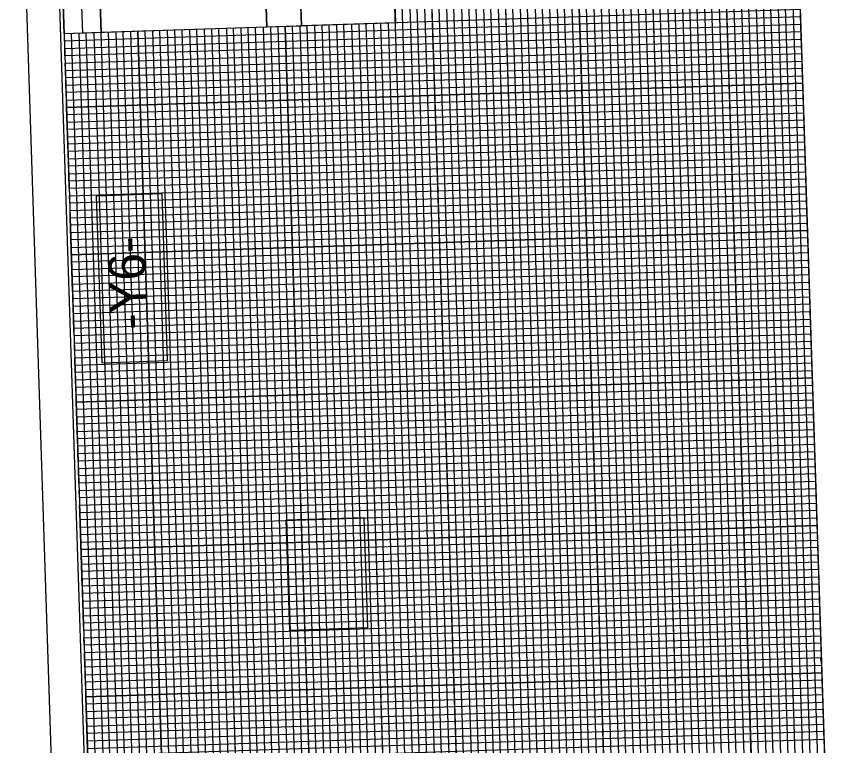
# Model space of a CAD drawing. Extents: x 1627314 to 1628469, y 762309 to 764247.
# Drawn here: x 1627314 to 1627864, y 763293 to 763788 of the extents above; entities that cross this region are included whole.
import ezdxf

# ---------------------------------------------------------------- set-up
doc = ezdxf.new("R2010")
doc.units = 0
for name, color, linetype in [('Old_Level_2', 7, 'Continuous'), ('Prop Grid Mask', 7, 'Continuous'), ('Sheet Data Field CELL', 7, 'Continuous'), ('Sheet DOT Grid CELL', 7, 'Continuous'), ('Sheet Layout Profile Border Port 1', 7, 'Continuous'), ('Sheet Plot Border Inside CELL', 7, 'Continuous'), ('Sheet Plot Border Outside CELL', 7, 'Continuous'), ('Sheet Profile CELL', 7, 'Continuous'), ('Sheet Profile Grid Major CELL', 7, 'Continuous'), ('Sheet Profile Grid Middle CELL', 7, 'Continuous'), ('Sheet Profile Grid Minor CELL', 7, 'Continuous'), ('Sheet Sticker Exception Certification CELL', 7, 'Continuous')]:
    doc.layers.add(name, color=color, linetype=linetype)

msp = doc.modelspace()

# ---------------------------------------------------------------- linework, layer by layer
at = {"layer": 'Old_Level_2'}
msp.add_lwpolyline([(1627507.79, 763781.61), (1627501.25, 763981.49), (1627565.16, 763983.58), (1627571.7, 763783.7)], close=True, dxfattribs=at)
at = {"layer": 'Prop Grid Mask'}
for points in [[(1627417.01, 763554.6), (1627413.31, 763667.62), (1627368.59, 763666.16), (1627372.29, 763553.14)], [(1627499.94, 763371.54), (1627497.49, 763446.59), (1627550.13, 763448.31), (1627552.58, 763373.26)]]:
    msp.add_lwpolyline(points, close=True, dxfattribs=at)
at = {"layer": 'Sheet DOT Grid CELL'}
for p, q in [((1627690.1, 763987.68), (1627739.13, 762488.48)), ((1627740.07, 763989.32), (1627789.11, 762490.12)), ((1627790.04, 763990.95), (1627839.08, 762491.75)), ((1627590.15, 763984.41), (1627639.19, 762485.21)), ((1627640.12, 763986.05), (1627689.16, 762486.85)), ((1627846.55, 763792.69), (1627484.3, 763780.84)), ((1627446.77, 763779.57), (1627489.27, 762480.31)), ((1627496.74, 763781.25), (1627539.24, 762481.95)), ((1627546.72, 763782.83), (1627589.21, 762483.58)), ((1627396.8, 763777.93), (1627439.29, 762478.68)), ((1627848.19, 763742.72), (1627348.46, 763726.37)), ((1627849.82, 763692.75), (1627350.09, 763676.4)), ((1627851.46, 763642.77), (1627351.73, 763626.43)), ((1627853.09, 763592.8), (1627353.36, 763576.45)), ((1627854.73, 763542.83), (1627354.99, 763526.48)), ((1627856.36, 763492.85), (1627356.63, 763476.51)), ((1627858, 763442.88), (1627358.26, 763426.53)), ((1627859.63, 763392.91), (1627359.9, 763376.56)), ((1627861.27, 763342.93), (1627361.53, 763326.59))]:
    msp.add_line(p, q, dxfattribs=at)
at = {"layer": 'Sheet Layout Profile Border Port 1'}
msp.add_lwpolyline([(1627548.65, 762532.28), (1627887.42, 762543.36), (1627841.65, 763942.61), (1627566.8, 763933.62)], dxfattribs=at)
at = {"layer": 'Sheet Plot Border Inside CELL'}
msp.add_lwpolyline([(1628446.34, 762357.53), (1628391.86, 764023.14), (1627337.33, 763988.65), (1627391.81, 762323.04)], close=True, dxfattribs=at)
at = {"layer": 'Sheet Plot Border Outside CELL'}
msp.add_lwpolyline([(1628469.21, 762345.27), (1628413.63, 764044.37), (1627314.22, 764008.4), (1627369.79, 762309.31)], close=True, dxfattribs=at)
at = {"layer": 'Sheet Profile CELL'}
for p, q in [((1627889.05, 762493.39), (1627840.02, 763992.59)), ((1627359.37, 763776.71), (1627352.83, 763976.65))]:
    msp.add_line(p, q, dxfattribs=at)
for points in [[(1627340.28, 763976.24), (1627389.32, 762477.04), (1628438.76, 762511.37), (1628389.72, 764010.57)], [(1627346.82, 763776.3), (1627340.28, 763976.24), (1627365.32, 763977.06), (1627371.86, 763777.12)], [(1627371.86, 763777.12), (1627368.59, 763877.11), (1627481.03, 763880.79), (1627484.3, 763780.79)]]:
    msp.add_lwpolyline(points, close=True, dxfattribs=at)
at = {"layer": 'Sheet Profile Grid Major CELL'}
for points in [[(1627640.12, 763986.05), (1627689.16, 762486.85), (1627739.13, 762488.48), (1627690.1, 763987.68)], [(1627740.07, 763989.32), (1627789.11, 762490.12), (1627789.11, 762490.12), (1627839.08, 762491.75), (1627790.04, 763990.95)], [(1627546.71, 763782.88), (1627589.21, 762483.58), (1627639.19, 762485.21), (1627590.15, 763984.41)], [(1627363.17, 763276.61), (1627361.53, 763326.59), (1627861.27, 763342.93), (1627859.63, 763392.91), (1627359.9, 763376.56), (1627358.26, 763426.53), (1627858, 763442.88), (1627856.36, 763492.85), (1627356.63, 763476.51), (1627354.99, 763526.48), (1627854.73, 763542.83), (1627853.09, 763592.8), (1627353.36, 763576.45), (1627351.73, 763626.43), (1627851.46, 763642.77), (1627849.82, 763692.75), (1627350.09, 763676.4), (1627348.46, 763726.37), (1627848.19, 763742.72), (1627846.55, 763792.69), (1627346.82, 763776.35), (1627345.96, 763802.63)], [(1627439.29, 762478.68), (1627396.79, 763777.98)], [(1627446.77, 763779.62), (1627489.27, 762480.31), (1627539.24, 762481.95), (1627496.74, 763781.25)]]:
    msp.add_lwpolyline(points, dxfattribs=at)
at = {"layer": 'Sheet Profile Grid Middle CELL'}
msp.add_line((1627414.31, 762477.86), (1627371.81, 763777.11), dxfattribs=at)
for points in [[(1627715.08, 763988.5), (1627764.12, 762489.3), (1627814.09, 762490.94), (1627765.06, 763990.13)], [(1627815.03, 763991.77), (1627864.07, 762492.57)], [(1627615.14, 763985.23), (1627664.17, 762486.03), (1627714.15, 762487.67), (1627665.11, 763986.86)], [(1627863.72, 763267.97), (1627862.08, 763317.95), (1627362.35, 763301.6), (1627360.72, 763351.57), (1627860.45, 763367.92), (1627858.81, 763417.89), (1627359.08, 763401.55), (1627357.45, 763451.52), (1627857.18, 763467.87), (1627855.54, 763517.84), (1627355.81, 763501.49), (1627354.18, 763551.47), (1627853.91, 763567.81), (1627852.28, 763617.79), (1627352.54, 763601.44), (1627350.91, 763651.41), (1627850.64, 763667.76), (1627849.01, 763717.73), (1627349.27, 763701.39), (1627347.64, 763751.36), (1627847.37, 763767.71), (1627845.74, 763817.68), (1627570.88, 763808.69)], [(1627521.73, 763782.02), (1627564.23, 762482.76), (1627614.2, 762484.4), (1627570.88, 763808.69)], [(1627421.78, 763778.8), (1627464.28, 762479.49), (1627514.25, 762481.13), (1627471.75, 763780.43)]]:
    msp.add_lwpolyline(points, dxfattribs=at)
at = {"layer": 'Sheet Profile Grid Minor CELL'}
for p, q in [((1627742.5, 762538.62), (1627696.73, 763937.87)), ((1627701.73, 763938.04), (1627747.49, 762538.78)), ((1627752.49, 762538.95), (1627706.72, 763938.2)), ((1627711.72, 763938.36), (1627757.49, 762539.11)), ((1627767.48, 762539.44), (1627721.71, 763938.69)), ((1627726.71, 763938.85), (1627772.48, 762539.6)), ((1627731.71, 763939.02), (1627777.48, 762539.76)), ((1627736.71, 763939.18), (1627782.48, 762539.93)), ((1627792.47, 762540.25), (1627746.7, 763939.51)), ((1627751.7, 763939.67), (1627797.47, 762540.42)), ((1627802.47, 762540.58), (1627756.7, 763939.83)), ((1627761.69, 763940), (1627807.46, 762540.75)), ((1627817.46, 762541.07), (1627771.69, 763940.32)), ((1627776.69, 763940.49), (1627822.45, 762541.24)), ((1627827.45, 762541.4), (1627781.68, 763940.65)), ((1627786.68, 763940.81), (1627832.45, 762541.56)), ((1627842.44, 762541.89), (1627796.67, 763941.14)), ((1627801.67, 763941.3), (1627847.44, 762542.05)), ((1627852.44, 762542.22), (1627806.67, 763941.47)), ((1627811.67, 763941.63), (1627857.44, 762542.38)), ((1627867.43, 762542.71), (1627821.66, 763941.96)), ((1627826.66, 763942.12), (1627872.43, 762542.87)), ((1627877.42, 762543.03), (1627831.66, 763942.29)), ((1627576.79, 763933.95), (1627622.56, 762534.7)), ((1627627.56, 762534.86), (1627581.79, 763934.11)), ((1627586.79, 763934.28), (1627632.56, 762535.02)), ((1627642.55, 762535.35), (1627596.78, 763934.6)), ((1627601.78, 763934.77), (1627647.55, 762535.51)), ((1627652.55, 762535.68), (1627606.78, 763934.93)), ((1627611.77, 763935.09), (1627657.54, 762535.84)), ((1627667.54, 762536.17), (1627621.77, 763935.42)), ((1627626.77, 763935.58), (1627672.53, 762536.33)), ((1627677.53, 762536.5), (1627631.76, 763935.75)), ((1627636.76, 763935.91), (1627682.53, 762536.66)), ((1627692.52, 762536.99), (1627646.75, 763936.24)), ((1627651.75, 763936.4), (1627697.52, 762537.15)), ((1627702.52, 762537.31), (1627656.75, 763936.56)), ((1627661.75, 763936.73), (1627707.52, 762537.48)), ((1627717.51, 762537.8), (1627671.74, 763937.05)), ((1627676.74, 763937.22), (1627722.51, 762537.97)), ((1627727.51, 762538.13), (1627681.74, 763937.38)), ((1627686.73, 763937.55), (1627732.5, 762538.29)), ((1627481.75, 763780.71), (1627522.61, 762531.43)), ((1627486.75, 763780.92), (1627527.61, 762531.59)), ((1627491.74, 763781.09), (1627532.61, 762531.75)), ((1627542.6, 762532.08), (1627501.74, 763781.41)), ((1627506.74, 763781.58), (1627547.6, 762532.25)), ((1627552.6, 762532.41), (1627511.73, 763781.69)), ((1627531.72, 763782.34), (1627572.59, 762533.06)), ((1627577.59, 762533.23), (1627536.72, 763782.51)), ((1627556.71, 763783.16), (1627597.57, 762533.88)), ((1627602.57, 762534.04), (1627561.71, 763783.33)), ((1627392.68, 762527.18), (1627351.82, 763776.51)), ((1627356.82, 763776.67), (1627398.03, 762527.35)), ((1627402.68, 762527.5), (1627361.81, 763776.84))]:
    msp.add_line(p, q, dxfattribs=at)
for points in [[(1627836.65, 763942.45), (1627882.42, 762543.2)], [(1627566.71, 763783.49), (1627607.57, 762534.21), (1627617.56, 762534.53), (1627571.79, 763933.79)], [(1627850.15, 763682.75), (1627849.99, 763687.75), (1627350.25, 763671.4), (1627349.93, 763681.4), (1627849.66, 763697.74), (1627849.5, 763702.74), (1627349.76, 763686.39), (1627349.6, 763691.39), (1627849.33, 763707.74), (1627849.17, 763712.74), (1627349.44, 763696.39), (1627349.11, 763706.38), (1627848.84, 763722.73), (1627848.68, 763727.73), (1627348.95, 763711.38), (1627348.78, 763716.38), (1627848.52, 763732.72), (1627848.35, 763737.72), (1627348.62, 763721.38), (1627348.29, 763731.37), (1627848.03, 763747.72), (1627847.86, 763752.71), (1627348.13, 763736.37), (1627347.97, 763741.37), (1627847.7, 763757.71), (1627847.53, 763762.71), (1627347.8, 763746.36), (1627347.48, 763756.36), (1627847.21, 763772.7), (1627847.04, 763777.7), (1627347.31, 763761.35), (1627347.15, 763766.35), (1627846.88, 763782.7), (1627846.72, 763787.7), (1627346.98, 763771.35), (1627346.66, 763781.34)], [(1627391.8, 763777.82), (1627432.66, 762528.49), (1627442.66, 762528.81), (1627401.79, 763778.14)], [(1627406.79, 763778.31), (1627447.65, 762528.98), (1627452.65, 762529.14), (1627411.79, 763778.47)], [(1627416.78, 763778.63), (1627457.65, 762529.3), (1627467.64, 762529.63), (1627426.78, 763778.96)], [(1627431.78, 763779.13), (1627472.64, 762529.79), (1627477.64, 762529.96), (1627436.77, 763779.29)], [(1627441.77, 763779.45), (1627482.64, 762530.12), (1627492.63, 762530.45), (1627451.77, 763779.78)], [(1627456.86, 763779.95), (1627497.72, 762530.71), (1627502.62, 762530.87), (1627461.76, 763780.11)], [(1627466.76, 763780.27), (1627507.62, 762530.94), (1627517.62, 762531.26), (1627476.75, 763780.6)], [(1627516.73, 763781.85), (1627557.6, 762532.57), (1627567.59, 762532.9), (1627526.73, 763782.18)], [(1627541.72, 763782.67), (1627582.58, 762533.39), (1627592.58, 762533.72), (1627551.71, 763783)], [(1627366.81, 763777), (1627407.68, 762527.67), (1627417.67, 762528), (1627376.81, 763777.33)], [(1627381.8, 763777.44), (1627422.67, 762528.16), (1627427.67, 762528.32), (1627386.8, 763777.65)], [(1627860.12, 763377.91), (1627360.39, 763361.57), (1627360.23, 763366.57), (1627859.96, 763382.91), (1627859.79, 763387.91), (1627360.06, 763371.56), (1627359.73, 763381.56), (1627859.47, 763397.9), (1627859.3, 763402.9), (1627359.57, 763386.55), (1627359.41, 763391.55), (1627859.14, 763407.9), (1627858.98, 763412.9), (1627359.24, 763396.55), (1627358.92, 763406.54), (1627858.65, 763422.89), (1627858.49, 763427.89), (1627358.75, 763411.54), (1627358.59, 763416.54), (1627858.32, 763432.88), (1627858.16, 763437.88), (1627358.43, 763421.54), (1627358.1, 763431.53), (1627857.83, 763447.88), (1627857.67, 763452.87), (1627357.94, 763436.53), (1627357.77, 763441.53), (1627857.51, 763457.87), (1627857.34, 763462.87), (1627357.61, 763446.52), (1627357.28, 763456.52), (1627857.02, 763472.86), (1627856.85, 763477.86), (1627357.12, 763461.51), (1627356.96, 763466.51), (1627856.69, 763482.86), (1627856.53, 763487.86), (1627356.79, 763471.51), (1627356.47, 763481.5), (1627856.2, 763497.85), (1627856.03, 763502.85), (1627356.3, 763486.5), (1627356.14, 763491.5), (1627855.87, 763507.84), (1627855.71, 763512.84), (1627355.98, 763496.5), (1627355.65, 763506.49), (1627855.38, 763522.84), (1627855.22, 763527.83), (1627355.48, 763511.49), (1627355.32, 763516.49), (1627855.05, 763532.83), (1627854.89, 763537.83), (1627355.16, 763521.48), (1627354.83, 763531.48), (1627854.56, 763547.82), (1627854.4, 763552.82), (1627354.67, 763536.47), (1627354.5, 763541.47), (1627854.24, 763557.82), (1627854.07, 763562.82), (1627354.34, 763546.47), (1627354.01, 763556.46), (1627853.75, 763572.81), (1627853.58, 763577.81), (1627353.85, 763561.46), (1627353.69, 763566.46), (1627853.42, 763582.8), (1627853.26, 763587.8), (1627353.52, 763571.46), (1627353.2, 763581.45), (1627852.93, 763597.8), (1627852.77, 763602.79), (1627353.03, 763586.45), (1627352.87, 763591.45), (1627852.6, 763607.79), (1627852.44, 763612.79), (1627352.71, 763596.44), (1627352.38, 763606.44), (1627852.11, 763622.78), (1627851.95, 763627.78), (1627352.22, 763611.43), (1627352.05, 763616.43), (1627851.78, 763632.78), (1627851.62, 763637.78), (1627351.89, 763621.43), (1627351.56, 763631.42), (1627851.29, 763647.77), (1627851.13, 763652.77), (1627351.4, 763636.42), (1627351.23, 763641.42), (1627850.97, 763657.76), (1627850.8, 763662.76), (1627351.07, 763646.42), (1627350.74, 763656.41), (1627850.48, 763672.76), (1627850.31, 763677.75), (1627350.58, 763661.41), (1627350.42, 763666.41), (1627850.15, 763682.75)], [(1627362.68, 763291.61), (1627862.41, 763307.95), (1627862.25, 763312.95), (1627362.51, 763296.6), (1627362.19, 763306.6), (1627861.92, 763322.94), (1627861.76, 763327.94), (1627362.02, 763311.59), (1627361.86, 763316.59), (1627861.59, 763332.94), (1627861.43, 763337.94), (1627361.7, 763321.59), (1627361.37, 763331.58), (1627861.1, 763347.93), (1627860.4, 763352.61), (1627860.94, 763352.93), (1627361.21, 763336.58), (1627361.04, 763341.58), (1627860.78, 763357.93), (1627860.61, 763362.92), (1627360.88, 763346.58), (1627360.55, 763356.57), (1627860.28, 763372.92), (1627860.12, 763377.91)], [(1627363, 763281.61), (1627862.74, 763297.96), (1627862.57, 763302.95), (1627362.84, 763286.61)]]:
    msp.add_lwpolyline(points, dxfattribs=at)
at = {"layer": 'Sheet Sticker Exception Certification CELL'}
for p, q in [((1627484.3, 763780.79), (1627477.76, 763980.72)), ((1627484.3, 763780.79), (1627477.76, 763980.72)), ((1627501.25, 763981.49), (1627507.79, 763781.56)), ((1627501.25, 763981.49), (1627507.79, 763781.56)), ((1627507.79, 763781.56), (1627484.3, 763780.79)), ((1627507.79, 763781.56), (1627484.3, 763780.79))]:
    msp.add_line(p, q, dxfattribs=at)

# ---------------------------------------------------------------- texts
at = {"layer": 'Sheet Data Field CELL'}
msp.add_text('-Y6-', height=25, rotation=91.8735, dxfattribs=at).set_placement((1627403.25, 763575.89))

doc.saveas('drawing.dxf')
